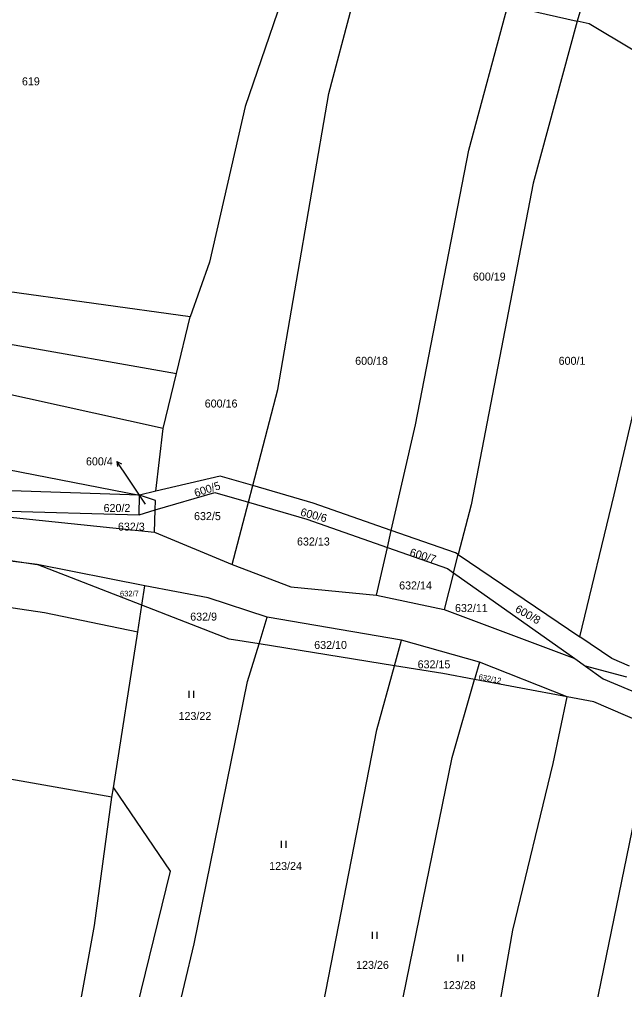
# Model space of a CAD drawing. Extents: x -746176 to -739709, y -1128407 to -1124482.
# Drawn here: x -742602.7 to -742474.2, y -1127345.9 to -1127139.9 of the extents above; entities that cross this region are included whole.
import ezdxf

# ---------------------------------------------------------------- set-up
doc = ezdxf.new("R2010")
doc.units = 0
for name, color, linetype in [('Hranice parcel', 7, 'Continuous'), ('Parcelní čísla', 7, 'Continuous'), ('Pop  PČ popisy', 7, 'Continuous'), ('Značky kultur', 7, 'Continuous')]:
    doc.layers.add(name, color=color, linetype=linetype)

msp = doc.modelspace()

# ---------------------------------------------------------------- linework, layer by layer
at = {"layer": 'Hranice parcel'}
for p, q in [((-742477.79, -1127119.09), (-742484.3, -1127140.22)), ((-742498.96, -1127136.92), (-742484.3, -1127140.22)), ((-742566.48, -1127203.04), (-742644.1, -1127192.22)), ((-742569.32, -1127215.09), (-742566.48, -1127203.04)), ((-742572.17, -1127226.73), (-742569.32, -1127215.09)), ((-742573.72, -1127240.07), (-742572.17, -1127226.73)), ((-742573.72, -1127240.07), (-742577.19, -1127240.89)), ((-742554.07, -1127242.4), (-742553.15, -1127238.87)), ((-742577.26, -1127245.05), (-742577.19, -1127240.89)), ((-742557.53, -1127255.65), (-742554.07, -1127242.4)), ((-742678.76, -1127243.56), (-742598.97, -1127255.65)), ((-742621.56, -1127243.8), (-742574.02, -1127248.78)), ((-742621.56, -1127243.8), (-742577.26, -1127245.05)), ((-742577.26, -1127245.05), (-742573.86, -1127244.05)), ((-742574.02, -1127248.78), (-742573.86, -1127244.05)), ((-742574.02, -1127248.78), (-742557.53, -1127255.65)), ((-742524.58, -1127252.01), (-742523.75, -1127248.38)), ((-742526.9, -1127262.12), (-742524.58, -1127252.01)), ((-742510.5, -1127257.39), (-742509.51, -1127253.53)), ((-742509.51, -1127253.53), (-742483.68, -1127270.99)), ((-742576.08, -1127260.13), (-742598.97, -1127255.65)), ((-742576.72, -1127264.27), (-742598.97, -1127255.65)), ((-742510.5, -1127257.39), (-742512.49, -1127265.17)), ((-742510.5, -1127257.39), (-742484.78, -1127275.57)), ((-742576.72, -1127264.27), (-742576.08, -1127260.13)), ((-742526.9, -1127262.12), (-742512.49, -1127265.17)), ((-742577.59, -1127269.9), (-742576.72, -1127264.27)), ((-742512.49, -1127265.17), (-742484.78, -1127275.57)), ((-742551.83, -1127272.48), (-742550.1, -1127266.78)), ((-742521.55, -1127271.68), (-742550.1, -1127266.78)), ((-742582.72, -1127303.04), (-742577.59, -1127269.9)), ((-742523.05, -1127277.11), (-742551.83, -1127272.48)), ((-742523.05, -1127277.11), (-742521.55, -1127271.68)), ((-742504.98, -1127276.38), (-742521.55, -1127271.68)), ((-742484.78, -1127275.57), (-742482.5, -1127277.19)), ((-742504.98, -1127276.38), (-742506.04, -1127280.03)), ((-742486.41, -1127283.7), (-742504.98, -1127276.38)), ((-742473.74, -1127279.57), (-742482.5, -1127277.19)), ((-742486.41, -1127283.7), (-742506.04, -1127280.03)), ((-742583.12, -1127305.02), (-742582.72, -1127303.04))]:
    msp.add_line(p, q, dxfattribs=at)
for points in [[(-742543.65, -1127125.88), (-742554.78, -1127158.4), (-742562.37, -1127191.45), (-742566.48, -1127203.04)], [(-742553.15, -1127238.87), (-742547.82, -1127218.47), (-742536.99, -1127155.61), (-742532.11, -1127137.2)], [(-742523.75, -1127248.38), (-742518.59, -1127225.94), (-742507.29, -1127167.65), (-742498.96, -1127136.92)], [(-742484.3, -1127140.22), (-742493.61, -1127174.67), (-742506.81, -1127242.95), (-742509.51, -1127253.53)], [(-742454.04, -1127157.35), (-742481.72, -1127140.8), (-742484.3, -1127140.22)], [(-742483.68, -1127270.99), (-742476.39, -1127240.81), (-742460.54, -1127173), (-742454.04, -1127157.35)], [(-742725.69, -1127194.04), (-742650.94, -1127202.29), (-742606.23, -1127208.56), (-742569.32, -1127215.09)], [(-742572.17, -1127226.73), (-742608.43, -1127218.73), (-742647.39, -1127212.79), (-742690.57, -1127207.86)], [(-742664.96, -1127226.26), (-742655.98, -1127227.12), (-742608.13, -1127234.85), (-742577.19, -1127240.89)], [(-742577.19, -1127240.89), (-742621.26, -1127239.44), (-742638.6, -1127238), (-742659.14, -1127230.44), (-742664.96, -1127226.26)], [(-742553.15, -1127238.87), (-742560.09, -1127236.86), (-742573.72, -1127240.07)], [(-742573.86, -1127244.05), (-742561.22, -1127240.32), (-742554.07, -1127242.4)], [(-742523.75, -1127248.38), (-742540.33, -1127242.59), (-742553.15, -1127238.87)], [(-742573.86, -1127244.05), (-742573.79, -1127242.02), (-742577.19, -1127240.89)], [(-742554.07, -1127242.4), (-742541.7, -1127246.01), (-742524.58, -1127252.01)], [(-742598.97, -1127255.65), (-742642.9, -1127250.2), (-742660.81, -1127251.7), (-742678.76, -1127243.56)], [(-742509.51, -1127253.53), (-742510.08, -1127253.15), (-742523.75, -1127248.38)], [(-742736.14, -1127250.3), (-742715.39, -1127251.55), (-742655.59, -1127257.18), (-742597.39, -1127265.81), (-742577.59, -1127269.9)], [(-742524.58, -1127252.01), (-742511.77, -1127256.49), (-742510.5, -1127257.39)], [(-742557.53, -1127255.65), (-742545.05, -1127260.38), (-742526.9, -1127262.12)], [(-742550.1, -1127266.78), (-742562.63, -1127262.7), (-742576.08, -1127260.13)], [(-742551.83, -1127272.48), (-742558.2, -1127271.45), (-742576.72, -1127264.27)], [(-742473.15, -1127277.19), (-742476.88, -1127275.58), (-742483.68, -1127270.99)], [(-742571.73, -1127362.05), (-742565.58, -1127336.15), (-742554.25, -1127280.44), (-742551.83, -1127272.48)], [(-742543.19, -1127372.64), (-742538.11, -1127348.86), (-742526.83, -1127290.76), (-742523.05, -1127277.11)], [(-742506.04, -1127280.03), (-742512.81, -1127278.76), (-742523.05, -1127277.11)], [(-742482.5, -1127277.19), (-742478.71, -1127279.87), (-742435.6, -1127297.95), (-742390.76, -1127324.91), (-742338.36, -1127352.64), (-742294.93, -1127366.2), (-742262.34, -1127370.73), (-742214.62, -1127379.37), (-742176.91, -1127386.35)], [(-742530.91, -1127395.09), (-742510.84, -1127296.63), (-742506.04, -1127280.03)], [(-742583.12, -1127305.02), (-742639.33, -1127295.15), (-742725.03, -1127283.28)], [(-742511.41, -1127409.84), (-742497.94, -1127333.24), (-742489.37, -1127297.91), (-742486.41, -1127283.7)], [(-742467.25, -1127290.58), (-742480.76, -1127284.76), (-742486.41, -1127283.7)], [(-742492.74, -1127410.43), (-742471.55, -1127307.03), (-742467.25, -1127290.58)], [(-742582.72, -1127303.04), (-742570.71, -1127320.74), (-742580.44, -1127360.6), (-742571.73, -1127362.05)], [(-742593.77, -1127370.76), (-742586.78, -1127332.31), (-742583.12, -1127305.02)]]:
    msp.add_lwpolyline(points, dxfattribs=at)
at = {"layer": 'Pop  PČ popisy'}
for p, q in [((-742580.36, -1127236.21), (-742582.04, -1127233.72)), ((-742582.04, -1127233.72), (-742581.06, -1127234.27)), ((-742582.04, -1127233.72), (-742581.89, -1127234.83)), ((-742575.92, -1127242.8), (-742580.36, -1127236.21))]:
    msp.add_line(p, q, dxfattribs=at)
at = {"layer": 'Značky kultur'}
for p, q in [((-742566.69, -1127283.93), (-742566.69, -1127282.43)), ((-742565.69, -1127283.93), (-742565.69, -1127282.43)), ((-742547.04, -1127315.8), (-742547.04, -1127314.3)), ((-742546.04, -1127315.8), (-742546.04, -1127314.3)), ((-742527.75, -1127335.11), (-742527.75, -1127333.61)), ((-742526.75, -1127335.11), (-742526.75, -1127333.61)), ((-742509.55, -1127339.91), (-742509.55, -1127338.41)), ((-742508.55, -1127339.91), (-742508.55, -1127338.41))]:
    msp.add_line(p, q, dxfattribs=at)

# ---------------------------------------------------------------- texts
at = {"layer": 'Parcelní čísla'}
for s, height, p in [('619', 1.7, (-742602.18, -1127153.88)), ('600/19', 1.7, (-742506.4, -1127195.34)), ('600/18', 1.7, (-742531.41, -1127213.22)), ('600/1', 1.7, (-742488.2, -1127213.22)), ('600/16', 1.7, (-742563.36, -1127222.29)), ('600/4', 1.7, (-742588.58, -1127234.57)), ('620/2', 1.7, (-742584.84, -1127244.48)), ('632/5', 1.7, (-742565.63, -1127246.2)), ('632/3', 1.7, (-742581.79, -1127248.43)), ('632/13', 1.7, (-742543.76, -1127251.59)), ('632/14', 1.7, (-742522.07, -1127260.92)), ('632/7', 1.19, (-742581.35, -1127262.4)), ('632/11', 1.7, (-742510.21, -1127265.72)), ('632/9', 1.7, (-742566.44, -1127267.54)), ('632/10', 1.7, (-742540.11, -1127273.56)), ('632/15', 1.7, (-742518.15, -1127277.67)), ('123/22', 1.7, (-742568.92, -1127288.65)), ('123/24', 1.7, (-742549.67, -1127320.5)), ('123/26', 1.7, (-742531.21, -1127341.5)), ('123/28', 1.7, (-742512.77, -1127345.79))]:
    msp.add_text(s, height=height, dxfattribs=at).set_placement(p)
for s, height, rotation, p in [('600/5', 1.7, 18, (-742565.27, -1127241.33)), ('600/6', 1.7, 345, (-742543.16, -1127245.22)), ('600/7', 1.7, 343, (-742519.97, -1127253.75)), ('600/8', 1.7, 330, (-742497.6, -1127265.55)), ('632/12', 1.19, 349, (-742505.27, -1127280))]:
    msp.add_text(s, height=height, rotation=rotation, dxfattribs=at).set_placement(p)

doc.saveas('drawing.dxf')
